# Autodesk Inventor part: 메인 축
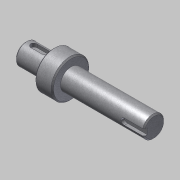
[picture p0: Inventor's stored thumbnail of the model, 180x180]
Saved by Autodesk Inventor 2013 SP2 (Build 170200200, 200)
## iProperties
Created: 2016-04
Part Number: 메인 축
Document SubType Name: Modeling
Designer: mdu
Density: 7.86 g/cm^3
Mass: 230.24 g
Surface Area: 74.3518 cm^2
Volume: 29.2926 cm^3
Material: 강철, 연강
Author: mdu
Revision Number: 1
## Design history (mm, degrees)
sketch "스케치1"
  geometry: L1 (10.497, -57.5)-(112.497, -57.5); L2 (10.497, -66)-(32.497, -66); L3 (32.497, -72.5)-(46.5, -72.5); L4 (46.5, -66)-(112.497, -66); L5 (112.497, -66)-(112.497, -57.5); L6 (10.497, -66)-(10.497, -57.5); L7 (46.5, -69.749)-(46.5, -45.251) reference; L8 (46.5, -72.5)-(46.5, -66); L9 (32.497, -72.5)-(32.497, -66); L10 (32.497, -35)-(32.497, -80) reference; 3 further points
  constraints: 16 end point, 3 point on line, 2 parallel, 2 perpendicular, 1 collinear, 1 horizontal, 1 midpoint
  dimensions: "d0" = 17 diameter of L4 L1; "d1" = 30 diameter of L3 L1; "d2" = 22 distance of L2.start L2.end; "d3" = 65.99692 distance of L4.start L4.end (derived); "d5" = 17 diameter of L2 L1; "d19" = 80 distance between parallel lines of L5 L9
revolve "회전1" sketch "스케치1" stored, may be unused: angle "d4" = 90 deg
chamfer "모따기1" distance "d6" = 1; stored, may be unused: second distance "d7" = 2, angle "d8" = 45 deg
node "작업 평면1"
sketch "스케치2"
  geometry: L1 (-11, -7.5)-(-11, 7.5) reference; L2 (-4.5, 2.5)-(4.5, 2.5); L3 (4.5, -2.5)-(-4.5, -2.5); A1 r 2.5 centre (4.5, 0) between (4.5, -2.5) and (4.5, 2.5); A2 r 2.5 centre (-4.5, 0) between (-4.5, 2.5) and (-4.5, -2.5); 2 further points
  constraints: 4 end point, 4 point on circle, 4 tangent, 2 centre point, 1 horizontal alignment, 1 midpoint, 1 parallel, 1 perpendicular
  dimensions: "d9" = 5 distance between parallel lines of L3 L2; "d10" = 14 dimension on A1 A2; "d11" = 4 distance edge to line of A2 L1
extrude "돌출1" cut sketch "스케치2" distance "d12" = 3; taper "d13" = 0 deg
node "작업 평면2"
sketch "스케치3"
  geometry: L1 (32.998, 7.5)-(32.998, -7.5) reference; L2 (32.998, 2.5)-(17.498, 2.5); L3 (17.498, -2.5)-(32.998, -2.5); A1 r 2.5 centre (17.498, 0) between (17.498, 2.5) and (17.498, -2.5); 2 further points
  constraints: 4 end point, 2 perpendicular, 2 point on circle, 2 point on line, 2 tangent, 1 centre point, 1 horizontal alignment, 1 midpoint
  dimensions: "d14" = 5 distance between parallel lines of L3 L2; "d15" = 18 dimension on A1 L1
extrude "돌출2" cut sketch "스케치3" distance "d16" = 3; taper "d17" = 0 deg
node "솔리드1"
node "참조4"
node "참조5"
